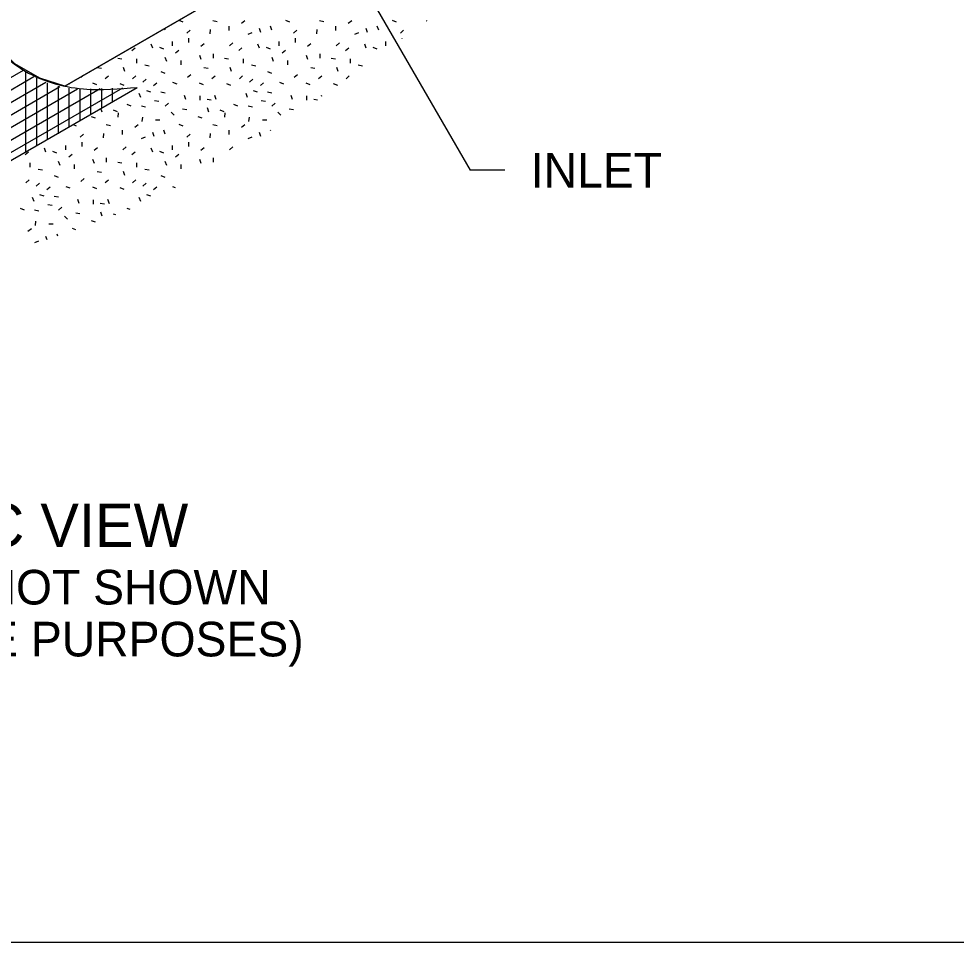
# Model space of a CAD drawing. Extents: x 99862 to 103151, y 100000 to 102076.
# Drawn here: x 102097.1 to 102530.3, y 99999.5 to 100426.3 of the extents above; entities that cross this region are included whole.
import ezdxf

# ---------------------------------------------------------------- set-up
doc = ezdxf.new("R2010")
doc.units = 0
for name, color, linetype in [('Level 1', 7, 'Continuous'), ('Level 15', 7, 'Continuous'), ('Level 2', 7, 'Continuous'), ('Level 20', 7, 'Continuous'), ('Level 3', 7, 'Continuous'), ('Level 5', 7, 'Continuous')]:
    doc.layers.add(name, color=color, linetype=linetype)

msp = doc.modelspace()

# ---------------------------------------------------------------- linework, layer by layer
at = {"layer": 'Level 1'}
msp.add_lwpolyline([(99862, 99999.5), (103151, 99999.5), (103151, 102075.5), (99862, 102075.5)], close=True, dxfattribs=at)
at = {"layer": 'Level 15'}
for p in [(102229.38, 100488.38), (102321.66, 100356.27)]:
    msp.add_line(p, (102305.66, 100356.27), dxfattribs=at)
at = {"layer": 'Level 2'}
msp.add_line((102118.33, 100395.2), (102370.55, 100540.82), dxfattribs=at)
msp.add_lwpolyline([(102093.43, 100700.82), (102370.55, 100540.82), (102118.33, 100395.2), (102106.84, 100398.85), (102095.24, 100405.41), (102080.64, 100420.2), (102073.37, 100429.25), (102292.61, 100555.82), (102119.41, 100655.82), (101991.98, 100582.26), (102013.82, 100654.87)], close=True, dxfattribs=at)
at = {"layer": 'Level 3'}
for p, q in [((101972.18, 100329.17), (102099.21, 100402.51)), ((101972.18, 100323.39), (102104.09, 100399.55)), ((102100.41, 100364.86), (102100.41, 100401.71)), ((102105.41, 100367.75), (102105.41, 100398.86)), ((101972.18, 100317.62), (102109.63, 100396.98)), ((101972.18, 100311.85), (102116.13, 100394.96)), ((101972.18, 100290.82), (102151.86, 100394.56)), ((101972.18, 100294.53), (102145.12, 100394.37)), ((102110.41, 100370.63), (102110.41, 100396.68)), ((102115.41, 100373.52), (102115.41, 100395.13)), ((102120.41, 100376.41), (102120.41, 100394.19)), ((102140.41, 100387.95), (102140.41, 100394.24)), ((101972.18, 100300.3), (102134.62, 100394.08)), ((101972.18, 100306.07), (102124.26, 100393.88)), ((102125.41, 100379.29), (102125.41, 100393.85)), ((102130.41, 100382.18), (102130.41, 100393.96)), ((102135.41, 100385.07), (102135.41, 100394.1))]:
    msp.add_line(p, q, dxfattribs=at)
msp.add_spline([(101972.18, 100490.82), (101998.36, 100488.67), (102027.36, 100479.96), (102054.43, 100456.74), (102076.18, 100425.79), (102098.42, 100403.06), (102126.93, 100393.87), (102151.86, 100394.56)], degree=3, dxfattribs=at)
at = {"layer": 'Level 5'}
for p, q in [((102171.06, 100425.65), (102172.85, 100424.93)), ((102186.77, 100425.43), (102188.74, 100425.07)), ((102201.6, 100425.32), (102199.96, 100424.17)), ((102220.31, 100425.68), (102222.16, 100424.93)), ((102236.08, 100425.43), (102238.05, 100425.07)), ((102250.92, 100425.32), (102249.28, 100424.17)), ((102269.62, 100425.68), (102271.48, 100424.93)), ((102285.4, 100425.43), (102285.58, 100425.4)), ((102164.76, 100420.99), (102164.46, 100421.84)), ((102174.79, 100419.7), (102176.25, 100421.06)), ((102185.56, 100421.34), (102185.36, 100419.35)), ((102194.1, 100422.89), (102194.1, 100420.89)), ((102208.95, 100419.88), (102208.28, 100421.76)), ((102214.08, 100420.99), (102213.41, 100422.87)), ((102224.1, 100419.7), (102225.57, 100421.06)), ((102234.87, 100421.34), (102234.68, 100419.35)), ((102243.41, 100422.89), (102243.41, 100420.89)), ((102258.27, 100419.88), (102257.6, 100421.76)), ((102263.39, 100420.99), (102262.72, 100422.87)), ((102273.42, 100419.7), (102274.88, 100421.06)), ((102167.96, 100415.85), (102167.96, 100413.85)), ((102175.5, 100417.26), (102175.5, 100415.26)), ((102203.12, 100419.09), (102204.96, 100419.86)), ((102217.28, 100415.85), (102217.28, 100413.85)), ((102224.82, 100417.26), (102224.82, 100415.26)), ((102252.43, 100419.09), (102254.28, 100419.86)), ((102266.6, 100415.85), (102266.6, 100413.85)), ((102274.13, 100417.26), (102274.13, 100417.11)), ((102149.37, 100411.59), (102150.89, 100412.9)), ((102158.97, 100412.74), (102158.29, 100414.62)), ((102162.05, 100413.11), (102163.9, 100412.36)), ((102169.54, 100410.49), (102171.06, 100411.79)), ((102181.2, 100413.61), (102182.72, 100414.91)), ((102194.47, 100413.81), (102195.99, 100415.11)), ((102198.69, 100411.59), (102200.21, 100412.9)), ((102208.28, 100412.74), (102207.61, 100414.62)), ((102211.36, 100413.11), (102213.22, 100412.36)), ((102218.86, 100410.49), (102220.38, 100411.79)), ((102230.52, 100413.61), (102232.04, 100414.91)), ((102243.78, 100413.81), (102245.3, 100415.11)), ((102248.01, 100411.59), (102249.52, 100412.9)), ((102257.6, 100412.74), (102256.92, 100414.62)), ((102260.68, 100413.11), (102262.54, 100412.36)), ((102142.78, 100408.13), (102144.75, 100407.78)), ((102151.51, 100407.71), (102151.51, 100405.71)), ((102165.47, 100406.5), (102164.79, 100408.39)), ((102181.35, 100407.41), (102180.67, 100409.29)), ((102186.86, 100410.12), (102186.86, 100408.12)), ((102192.1, 100408.13), (102194.06, 100407.78)), ((102200.83, 100407.71), (102200.83, 100405.71)), ((102214.78, 100406.5), (102214.11, 100408.39)), ((102230.66, 100407.41), (102229.99, 100409.29)), ((102236.17, 100410.12), (102236.17, 100408.12)), ((102241.41, 100408.13), (102243.38, 100407.78)), ((102250.14, 100407.71), (102250.14, 100405.71)), ((102133.33, 100403.81), (102135.3, 100403.45)), ((102146.1, 100401.88), (102145.43, 100403.76)), ((102155.34, 100404.92), (102157.31, 100404.56)), ((102171.98, 100407), (102171.98, 100405)), ((102182.65, 100403.81), (102184.62, 100403.45)), ((102195.42, 100401.88), (102194.74, 100403.76)), ((102204.66, 100404.92), (102206.63, 100404.56)), ((102221.3, 100407), (102221.3, 100405)), ((102231.96, 100403.81), (102233.93, 100403.45)), ((102244.73, 100401.88), (102244.06, 100403.76)), ((102253.97, 100404.92), (102255.94, 100404.56)), ((102125.76, 100399.23), (102126.7, 100400.04)), ((102137.01, 100398.62), (102138.53, 100399.92)), ((102149.69, 100398.48), (102151.16, 100399.84)), ((102162.75, 100401.94), (102164.61, 100401.2)), ((102175.07, 100399.23), (102176.59, 100400.53)), ((102186.33, 100398.62), (102187.85, 100399.92)), ((102199.01, 100398.48), (102200.47, 100399.84)), ((102212.07, 100401.94), (102213.92, 100401.2)), ((102224.39, 100399.23), (102225.91, 100400.53)), ((102235.64, 100398.62), (102237.16, 100399.92)), ((102248.32, 100398.48), (102249.79, 100399.84)), ((102120.3, 100396.34), (102120.72, 100396.17)), ((102131.12, 100396.61), (102132.98, 100395.87)), ((102143.79, 100396.41), (102145.64, 100395.67)), ((102154.4, 100397.01), (102155.92, 100398.31)), ((102159.39, 100395.4), (102160.91, 100396.71)), ((102168.18, 100396.91), (102170.04, 100396.17)), ((102180.44, 100396.61), (102182.3, 100395.87)), ((102193.1, 100396.41), (102194.96, 100395.67)), ((102203.72, 100397.01), (102205.23, 100398.31)), ((102208.71, 100395.4), (102210.23, 100396.71)), ((102217.49, 100396.91), (102219.35, 100396.17)), ((102229.76, 100396.61), (102231.61, 100395.87)), ((102242.42, 100396.41), (102244.28, 100395.67)), ((102153.44, 100389.91), (102152.77, 100391.79)), ((102156.05, 100393.19), (102157.91, 100392.45)), ((102162.75, 100392.45), (102164.72, 100392.09)), ((102174.31, 100389.01), (102173.64, 100390.89)), ((102180.73, 100390.61), (102180.73, 100388.61)), ((102188.28, 100388.91), (102187.61, 100390.79)), ((102202.75, 100389.91), (102202.08, 100391.79)), ((102205.36, 100393.19), (102207.22, 100392.45)), ((102212.06, 100392.45), (102214.03, 100392.09)), ((102223.63, 100389.01), (102222.95, 100390.89)), ((102230.04, 100390.61), (102230.04, 100388.61)), ((102237.1, 100390.29), (102236.92, 100390.79)), ((102147, 100386.86), (102148.86, 100386.11)), ((102153.74, 100386.01), (102155.7, 100385.65)), ((102159.83, 100388.52), (102161.8, 100388.17)), ((102164.72, 100385.95), (102166.24, 100387.25)), ((102184.06, 100389.13), (102186.02, 100388.77)), ((102196.32, 100386.86), (102198.18, 100386.11)), ((102203.05, 100386.01), (102205.02, 100385.65)), ((102209.15, 100388.52), (102211.12, 100388.17)), ((102214.04, 100385.95), (102215.55, 100387.25)), ((102233.37, 100389.13), (102235.06, 100388.82)), ((102135.65, 100383.17), (102135.05, 100384.86)), ((102140.67, 100384.24), (102142.53, 100383.5)), ((102142.98, 100382.82), (102142.78, 100380.83)), ((102168.9, 100381.7), (102167.55, 100383.17)), ((102172.7, 100384.7), (102174.67, 100384.34)), ((102184.96, 100383.17), (102184.29, 100385.06)), ((102189.99, 100384.24), (102191.84, 100383.5)), ((102192.29, 100382.82), (102192.1, 100380.83)), ((102218.22, 100381.7), (102216.86, 100383.17)), ((102222.01, 100384.7), (102223.98, 100384.34)), ((102122.16, 100377.41), (102123.53, 100376.86)), ((102130.46, 100381.15), (102132.34, 100380.48)), ((102137.45, 100377.36), (102139.42, 100377)), ((102152.29, 100377.25), (102150.65, 100376.1)), ((102154.19, 100380.82), (102153.94, 100378.83)), ((102160.33, 100379.55), (102162.33, 100379.55)), ((102170.99, 100377.6), (102172.85, 100376.86)), ((102179.77, 100381.15), (102181.66, 100380.48)), ((102186.77, 100377.36), (102188.74, 100377)), ((102201.6, 100377.25), (102199.96, 100376.1)), ((102203.5, 100380.82), (102203.25, 100378.83)), ((102209.64, 100379.55), (102211.64, 100379.55)), ((102115.45, 100372.91), (102115.26, 100373.43)), ((102125.47, 100371.63), (102126.94, 100372.99)), ((102136.24, 100373.27), (102136.05, 100371.28)), ((102144.78, 100374.82), (102144.78, 100372.82)), ((102159.64, 100371.81), (102158.97, 100373.69)), ((102164.76, 100372.91), (102164.09, 100374.8)), ((102174.79, 100371.63), (102176.25, 100372.99)), ((102185.56, 100373.27), (102185.36, 100371.28)), ((102194.1, 100374.82), (102194.1, 100372.82)), ((102208.95, 100371.81), (102208.28, 100373.69)), ((102213.53, 100374.46), (102213.41, 100374.8)), ((102126.19, 100369.19), (102126.19, 100367.19)), ((102153.8, 100371.01), (102155.65, 100371.78)), ((102175.5, 100369.19), (102175.5, 100367.19)), ((102203.12, 100371.01), (102204.96, 100371.78)), ((102100.06, 100363.52), (102101.58, 100364.82)), ((102109.65, 100364.67), (102108.98, 100366.55)), ((102112.73, 100365.03), (102114.59, 100364.29)), ((102118.65, 100367.78), (102118.65, 100365.78)), ((102131.89, 100365.53), (102133.41, 100366.84)), ((102145.15, 100365.73), (102146.67, 100367.04)), ((102149.37, 100363.52), (102150.89, 100364.82)), ((102158.97, 100364.67), (102158.29, 100366.55)), ((102162.05, 100365.03), (102163.9, 100364.29)), ((102167.96, 100367.78), (102167.96, 100365.78)), ((102181.2, 100365.53), (102182.72, 100366.84)), ((102194.47, 100365.73), (102195.99, 100367.04)), ((102102.2, 100359.63), (102102.2, 100357.63)), ((102116.15, 100358.43), (102115.48, 100360.32)), ((102120.23, 100362.42), (102121.75, 100363.72)), ((102132.03, 100359.34), (102131.36, 100361.22)), ((102137.54, 100362.05), (102137.54, 100360.05)), ((102142.78, 100360.06), (102144.75, 100359.7)), ((102151.51, 100359.63), (102151.51, 100357.63)), ((102165.47, 100358.43), (102164.79, 100360.32)), ((102169.54, 100362.42), (102171.06, 100363.72)), ((102181.35, 100359.34), (102180.67, 100361.22)), ((102186.86, 100362.05), (102186.86, 100360.05)), ((102106.03, 100356.84), (102108, 100356.48)), ((102122.67, 100358.93), (102122.67, 100356.93)), ((102133.33, 100355.74), (102135.3, 100355.38)), ((102146.1, 100353.81), (102145.43, 100355.69)), ((102155.34, 100356.84), (102157.31, 100356.48)), ((102171.98, 100358.93), (102171.98, 100356.93)), ((102100.38, 100350.41), (102101.84, 100351.77)), ((102113.44, 100353.87), (102115.29, 100353.13)), ((102125.76, 100351.15), (102127.27, 100352.45)), ((102137.01, 100350.55), (102138.53, 100351.85)), ((102149.69, 100350.41), (102151.16, 100351.77)), ((102162.75, 100353.87), (102164.61, 100353.13)), ((102105.08, 100348.94), (102106.6, 100350.24)), ((102110.08, 100347.33), (102111.6, 100348.63)), ((102118.86, 100348.84), (102120.72, 100348.1)), ((102131.12, 100348.54), (102132.98, 100347.8)), ((102143.79, 100348.34), (102145.64, 100347.6)), ((102154.4, 100348.94), (102155.92, 100350.24)), ((102159.39, 100347.33), (102160.91, 100348.63)), ((102168.18, 100348.84), (102169.38, 100348.36)), ((102104.12, 100341.84), (102103.45, 100343.72)), ((102106.73, 100345.12), (102108.59, 100344.38)), ((102113.43, 100344.37), (102115.4, 100344.01)), ((102125, 100340.93), (102124.32, 100342.82)), ((102131.41, 100342.54), (102131.41, 100340.54)), ((102138.97, 100340.83), (102138.29, 100342.72)), ((102153.44, 100341.84), (102152.77, 100343.72)), ((102156.05, 100345.12), (102157.91, 100344.38)), ((102097.69, 100338.78), (102099.54, 100338.04)), ((102104.42, 100337.94), (102106.39, 100337.58)), ((102110.52, 100340.45), (102112.49, 100340.09)), ((102115.4, 100337.88), (102116.92, 100339.18)), ((102134.74, 100341.05), (102136.71, 100340.7)), ((102147, 100338.78), (102148.4, 100338.22)), ((102119.58, 100333.63), (102118.23, 100335.1)), ((102123.38, 100336.63), (102125.35, 100336.27)), ((102135.65, 100335.1), (102134.98, 100336.98)), ((102140.67, 100336.17), (102141.73, 100335.75)), ((102104.87, 100332.75), (102104.62, 100330.76)), ((102111.01, 100331.47), (102113.01, 100331.47)), ((102121.68, 100329.53), (102123.27, 100328.89)), ((102130.46, 100333.08), (102132.34, 100332.41)), ((102102.97, 100329.17), (102101.33, 100328.02)), ((102110.21, 100324.05), (102109.65, 100325.62)), ((102115.08, 100325.86), (102114.78, 100326.72)), ((102104.49, 100322.94), (102106.33, 100323.71))]:
    msp.add_line(p, q, dxfattribs=at)

# ---------------------------------------------------------------- texts
at = {"layer": 'Level 20'}
msp.add_text('INLET', height=16, rotation=360, dxfattribs=at).set_placement((102333.66, 100348.27))
for s, height, p in [('ISOMETRIC VIEW', 20, (101951.03, 100182.22)), ('(ENTIRE FENCE NOT SHOWN', 16, (101910.35, 100155.6)), ('FOR ILLUSTRATIVE PURPOSES)', 16, (101895.82, 100131.6))]:
    msp.add_text(s, height=height, dxfattribs=at).set_placement(p)

doc.saveas('drawing.dxf')
